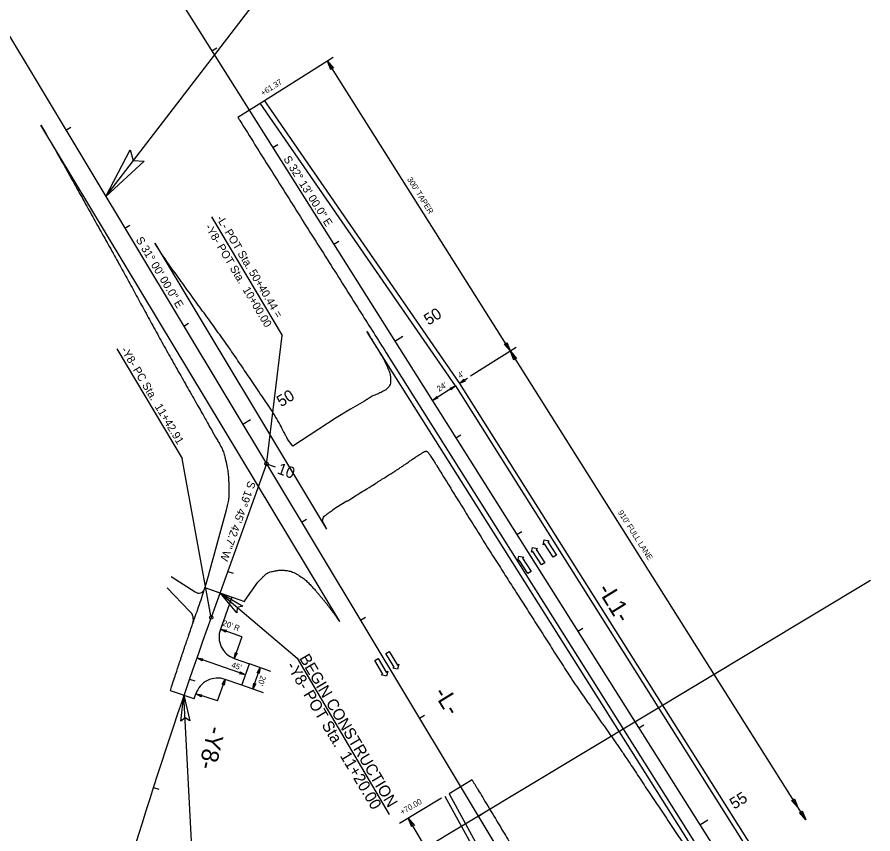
# Model space of a CAD drawing. Extents: x 1778969 to 1790720, y 807089 to 817794.
# Drawn here: x 1781066 to 1781814, y 813902 to 814616 of the extents above; entities that cross this region are included whole.
import ezdxf

# ---------------------------------------------------------------- set-up
doc = ezdxf.new("R2010")
doc.units = 0
for name, color, linetype in [('Default', 7, 'Continuous'), ('Prop Dimension', 7, 'Continuous'), ('Prop Dimension Text', 7, 'Continuous'), ('Prop EOT', 7, 'Continuous'), ('Prop Horizontal Alignment', 7, 'Continuous'), ('Prop Horizontal Alignment Direction Label', 7, 'Continuous'), ('Prop Horizontal Alignment Station Label', 7, 'Continuous'), ('Prop Horizontal Alignment Tick Label', 7, 'Continuous'), ('Prop Horizontal Alignment Tick Large', 7, 'Continuous'), ('Prop Horizontal Alignment Tick Small', 7, 'Continuous'), ('Prop Lane Arrow CELL', 7, 'Continuous'), ('Prop Paved Shoulder', 7, 'Continuous'), ('Prop Rem of Exist Asph Pvmt', 7, 'Continuous'), ('Prop Terminator CELL', 7, 'Continuous'), ('Scratch_Level_1', 7, 'Continuous')]:
    doc.layers.add(name, color=color, linetype=linetype)

msp = doc.modelspace()

# ---------------------------------------------------------------- linework, layer by layer
at = {"layer": 'Default'}
msp.add_line((1781346.69, 814088.87), (1781347.63, 814087.49), dxfattribs=at)
at = {"layer": 'Prop Dimension'}
for p, q in [((1781341.9, 814580.9), (1781281.87, 814543.07)), ((1781496.79, 814323.91), (1781336.86, 814577.72)), ((1781501.83, 814327.09), (1781462.04, 814302.01)), ((1781754.93, 813914.26), (1781496.79, 814323.91)), ((1781459.23, 814300.24), (1781452.3, 814295.87)), ((1781448.91, 814293.74), (1781428.61, 814280.94)), ((1781262.15, 814074.06), (1781243.31, 814080.8)), ((1781262.15, 814074.06), (1781255.49, 814055.2)), ((1781265.28, 814040.96), (1781222.81, 814055.83)), ((1781287.53, 814043.95), (1781268.66, 814050.56)), ((1781271.58, 814028.34), (1781278.19, 814047.22)), ((1781240.88, 814018.08), (1781247.45, 814036.97)), ((1781280.99, 814025.26), (1781262.11, 814031.87)), ((1781240.88, 814018.08), (1781221.86, 814024.26)), ((1781436.57, 813932.96), (1781399.86, 813910.91)), ((1781562.09, 813658.39), (1781407.57, 813915.54))]:
    msp.add_line(p, q, dxfattribs=at)
at = {"layer": 'Prop EOT'}
for p, q in [((1781281.87, 814543.07), (1781258.57, 814528.39)), ((1781448.91, 814293.74), (1781278.22, 814540.77)), ((1781388.28, 814322.43), (1781718.05, 813799.1)), ((1781448.91, 814293.74), (1781832.66, 813684.75)), ((1781200.42, 814127.05), (1781221.29, 814113.54)), ((1781196.86, 814117.14), (1781216.27, 814096.74)), ((1781229.78, 814117.37), (1781253.4, 814108.89)), ((1781253.4, 814108.89), (1781245.65, 814087.33)), ((1781217.08, 814079.71), (1781216.98, 814079.42)), ((1781255.49, 814055.2), (1781268.66, 814050.56)), ((1781262.11, 814031.87), (1781268.66, 814050.56)), ((1781262.11, 814031.87), (1781247.45, 814036.97)), ((1781220.45, 814019.94), (1781199.59, 814027.07)), ((1781220.45, 814019.94), (1781221.86, 814024.26)), ((1781463.3, 813949.03), (1781443.19, 813936.94)), ((1781443.19, 813936.94), (1781587.3, 813673.54))]:
    msp.add_line(p, q, dxfattribs=at)
for centre, radius, start, end in [((1781224.56, 814117.32), 5, 229.17438, 343.68233), ((1781209.73, 814089.17), 10, 341.35053, 49.17438), ((1785549.01, 812541.26), 4572.66, 160.23814, 160.32504), ((1781262.15, 814074.06), 20, 160.32504, 250.57674), ((1781240.88, 814018.08), 20, 70.82674, 161.99515)]:
    msp.add_arc(centre, radius, start, end, dxfattribs=at)
msp.add_spline([(1781258.57, 814528.39), (1781260.31, 814525.62), (1781286.77, 814483.59), (1781313.25, 814441.37), (1781340.02, 814399.05), (1781366.32, 814357.37), (1781388.28, 814322.43)], degree=3, dxfattribs=at)
for points in [[(1781199.59, 814027.07), (1781201.21, 814032.08), (1781202.84, 814037.08), (1781204.47, 814042.09), (1781208.13, 814053.3), (1781211.9, 814064.48), (1781215.69, 814075.65), (1781217.58, 814081.21), (1781219.55, 814086.75), (1781221.45, 814092.3), (1781224.25, 814100.43), (1781227.25, 814108.5), (1781229.61, 814116.76), (1781229.67, 814116.96), (1781229.72, 814117.17), (1781229.78, 814117.37)], [(1781463.3, 813949.03), (1781464.17, 813947.59), (1781465.05, 813946.15), (1781465.92, 813944.71), (1781474.8, 813929.99), (1781483.67, 813915.26), (1781492.5, 813900.51), (1781500.58, 813887.01), (1781508.59, 813873.47), (1781516.69, 813859.98), (1781525.21, 813845.83), (1781533.74, 813831.69), (1781542.26, 813817.54), (1781551.3, 813802.52), (1781560.33, 813787.49), (1781569.37, 813772.46), (1781578.14, 813757.89), (1781587.14, 813743.46), (1781595.91, 813728.89), (1781604.33, 813714.9), (1781612.49, 813700.76), (1781620.9, 813686.76), (1781629.44, 813672.57), (1781637.98, 813658.38), (1781646.54, 813644.19), (1781655.1, 813630), (1781663.72, 813615.84), (1781672.26, 813601.63), (1781680.69, 813587.61), (1781689, 813573.52), (1781697.41, 813559.48), (1781705.95, 813545.23), (1781714.52, 813530.99), (1781723.07, 813516.73), (1781731.64, 813502.44), (1781740.12, 813488.1), (1781748.7, 813473.81), (1781757.55, 813459.07), (1781766.63, 813444.47), (1781775.52, 813429.74), (1781784.14, 813415.46), (1781792.67, 813401.11), (1781801.32, 813386.83), (1781809.96, 813372.55), (1781818.65, 813358.29), (1781827.3, 813344.02), (1781835.99, 813329.66), (1781844.67, 813315.3), (1781853.35, 813300.93), (1781861.54, 813287.37), (1781869.6, 813273.73), (1781877.8, 813260.18), (1781886.68, 813245.53), (1781895.77, 813231.01), (1781904.68, 813216.38), (1781913.11, 813202.51), (1781921.54, 813188.63), (1781929.97, 813174.75), (1781938.85, 813160.12), (1781947.7, 813145.46), (1781956.59, 813130.83), (1781964.95, 813117.07), (1781973.52, 813103.43), (1781982.19, 813089.85), (1781991.2, 813075.72), (1782000.27, 813061.63), (1782009.36, 813047.54), (1782018.57, 813033.28), (1782027.8, 813019.03), (1782037.07, 813004.8), (1782046.22, 812990.76), (1782055.4, 812976.74), (1782064.84, 812962.89), (1782074.16, 812949.23), (1782083.5, 812935.58), (1782092.82, 812921.91), (1782102.18, 812908.19), (1782111.54, 812894.47), (1782120.9, 812880.75), (1782130.3, 812866.98), (1782139.85, 812853.32), (1782149.42, 812839.67), (1782158.88, 812826.17), (1782168.45, 812812.74), (1782178.15, 812799.41), (1782187.7, 812786.29), (1782197.57, 812773.41), (1782207.08, 812760.26), (1782216.45, 812747.28), (1782225.83, 812734.3), (1782235.2, 812721.32)]]:
    msp.add_open_spline(points, degree=3, dxfattribs=at)
at = {"layer": 'Prop Horizontal Alignment'}
for p, q in [((1780487.95, 815773.73), (1781812.35, 813671.96)), ((1780487.95, 815773.73), (1781812.35, 813671.96)), ((1780459.21, 815597.59), (1781830.87, 813314.76)), ((1780459.21, 815597.59), (1781830.87, 813314.76)), ((1781283.62, 814225.54), (1781235.3, 814091.04))]:
    msp.add_line(p, q, dxfattribs=at)
msp.add_arc((1785549.01, 812541.26), 4583.66, 160.23814, 164.70285, dxfattribs=at)
at = {"layer": 'Prop Horizontal Alignment Station Label'}
for p, q in [((1781143.14, 814459.33), (1781295.69, 814658.05)), ((1781235.5, 814441.55), (1781297.3, 814337.6)), ((1781283.8, 814227.03), (1781297.3, 814337.6)), ((1781152.75, 814326.03), (1781209.78, 814230.09)), ((1781235.03, 814092.52), (1781209.78, 814230.09)), ((1781243.05, 814112.61), (1781310.31, 814055.63)), ((1781310.31, 814055.63), (1781390.85, 813918.77)), ((1781222.21, 813816.09), (1781211.46, 814023.01))]:
    msp.add_line(p, q, dxfattribs=at)
for centre in [(1781283.62, 814225.54), (1781283.62, 814225.54), (1781235.3, 814091.04)]:
    msp.add_circle(centre, 1.5, dxfattribs=at)
at = {"layer": 'Prop Horizontal Alignment Tick Large'}
for p, q in [((1781395.89, 814332.87), (1781402.66, 814337.13)), ((1781262.79, 814260.2), (1781269.65, 814264.32)), ((1781283.62, 814225.54), (1781291.15, 814222.84)), ((1781283.62, 814225.54), (1781291.15, 814222.84)), ((1781662.45, 813909.85), (1781669.22, 813914.11))]:
    msp.add_line(p, q, dxfattribs=at)
at = {"layer": 'Prop Horizontal Alignment Tick Small'}
for p, q in [((1781235.95, 814586.68), (1781240.18, 814589.34)), ((1781108.28, 814517.35), (1781112.57, 814519.93)), ((1781289.27, 814502.07), (1781293.5, 814504.74)), ((1781159.79, 814431.64), (1781164.07, 814434.21)), ((1781342.58, 814417.47), (1781346.81, 814420.13)), ((1781211.29, 814345.92), (1781215.58, 814348.49)), ((1781449.2, 814248.26), (1781453.43, 814250.93)), ((1781314.3, 814174.49), (1781318.58, 814177.06)), ((1781502.52, 814163.66), (1781506.75, 814166.32)), ((1781249.81, 814131.43), (1781254.52, 814129.74)), ((1781365.8, 814088.77), (1781370.09, 814091.34)), ((1781555.83, 814079.05), (1781560.06, 814081.72)), ((1781216.33, 814037.2), (1781221.06, 814035.57)), ((1781417.3, 814003.05), (1781421.59, 814005.63)), ((1781609.14, 813994.45), (1781613.37, 813997.12)), ((1781184.73, 813942.33), (1781189.49, 813940.8)), ((1781468.81, 813917.34), (1781473.09, 813919.91))]:
    msp.add_line(p, q, dxfattribs=at)
at = {"layer": 'Prop Lane Arrow CELL'}
for p, q in [((1781515.15, 814148.07), (1781516.06, 814152.4)), ((1781516.06, 814152.4), (1781520.45, 814151.48)), ((1781525.48, 814154.7), (1781526.38, 814159.03)), ((1781526.74, 814155.51), (1781525.48, 814154.7)), ((1781526.38, 814159.03), (1781530.78, 814158.11)), ((1781534.31, 814143.73), (1781526.74, 814155.51)), ((1781530.78, 814158.11), (1781529.52, 814157.3)), ((1781529.52, 814157.3), (1781537.08, 814145.52)), ((1781503.33, 814140.48), (1781504.23, 814144.8)), ((1781504.23, 814144.8), (1781508.63, 814143.88)), ((1781516.41, 814148.88), (1781515.15, 814148.07)), ((1781523.98, 814137.1), (1781516.41, 814148.88)), ((1781520.45, 814151.48), (1781519.19, 814150.67)), ((1781519.19, 814150.67), (1781526.76, 814138.89)), ((1781537.08, 814145.52), (1781534.31, 814143.73)), ((1781504.59, 814141.29), (1781503.33, 814140.48)), ((1781512.16, 814129.51), (1781504.59, 814141.29)), ((1781508.63, 814143.88), (1781507.37, 814143.07)), ((1781507.37, 814143.07), (1781514.93, 814131.29)), ((1781526.76, 814138.89), (1781523.98, 814137.1)), ((1781514.93, 814131.29), (1781512.16, 814129.51)), ((1781378.25, 814053.59), (1781381.09, 814055.27)), ((1781381.09, 814055.27), (1781388.24, 814043.24)), ((1781388.02, 814059.7), (1781390.86, 814061.39)), ((1781395.18, 814047.67), (1781388.02, 814059.7)), ((1781390.86, 814061.39), (1781398.01, 814049.35)), ((1781385.4, 814041.55), (1781378.25, 814053.59)), ((1781393.89, 814046.9), (1781395.18, 814047.67)), ((1781398.01, 814049.35), (1781399.3, 814050.12)), ((1781399.3, 814050.12), (1781398.25, 814045.83)), ((1781384.11, 814040.79), (1781385.4, 814041.55)), ((1781388.48, 814039.71), (1781384.11, 814040.79)), ((1781388.24, 814043.24), (1781389.53, 814044.01)), ((1781389.53, 814044.01), (1781388.48, 814039.71)), ((1781398.25, 814045.83), (1781393.89, 814046.9))]:
    msp.add_line(p, q, dxfattribs=at)
at = {"layer": 'Prop Paved Shoulder'}
for p, q in [((1781281.87, 814543.07), (1781452.3, 814295.87)), ((1781452.3, 814295.87), (1781836.04, 813686.89)), ((1781439.63, 813934.8), (1781583.87, 813671.48))]:
    msp.add_line(p, q, dxfattribs=at)
at = {"layer": 'Prop Rem of Exist Asph Pvmt'}
for p, q in [((1781347.63, 814087.49), (1781086.3, 814521.67)), ((1781186.06, 814418.34), (1781336.16, 814168.44)), ((1781710.88, 813802.98), (1781371.34, 814341.26)), ((1781369.2, 814280.41), (1781356.96, 814273.28)), ((1781240.67, 814246.06), (1781241.22, 814245.41)), ((1781344.85, 814187.68), (1781353.97, 814192.98)), ((1781353.97, 814192.98), (1781354.7, 814193.2)), ((1781248.38, 814184.99), (1781233.25, 814129.52)), ((1781229.78, 814117.37), (1781264.25, 814104.99)), ((1781264.94, 814106.16), (1781276.07, 814122.01)), ((1781346.69, 814088.87), (1781347.63, 814087.49))]:
    msp.add_line(p, q, dxfattribs=at)
msp.add_lwpolyline([(1781356.96, 814273.28), (1781344.53, 814265.75), (1781306.61, 814240.93), (1781301.99, 814247.17)], dxfattribs=at)
for points, degree in [([(1781086.3, 814521.67), (1781092.84, 814510.56), (1781099.4, 814499.46), (1781105.7, 814488.21), (1781114.06, 814473.27), (1781122.35, 814458.29), (1781130.69, 814443.34), (1781139.04, 814428.38), (1781147.42, 814413.44), (1781155.75, 814398.47), (1781163.36, 814384.8), (1781170.69, 814370.97), (1781178.23, 814357.25), (1781186.23, 814342.69), (1781194.2, 814328.1), (1781202.39, 814313.64), (1781210.68, 814299), (1781218.98, 814284.38), (1781227.27, 814269.74), (1781231.74, 814261.85), (1781236.21, 814253.96), (1781240.67, 814246.06)], 3), ([(1781301.99, 814247.17), (1781300.93, 814249.17), (1781299.88, 814251.18), (1781298.83, 814253.18), (1781290.68, 814268.72), (1781280.64, 814283.19), (1781270.82, 814297.74), (1781262.02, 814310.79), (1781253.18, 814323.8), (1781244.04, 814336.62), (1781234.12, 814350.54), (1781223.91, 814364.26), (1781213.98, 814378.18), (1781204.51, 814391.45), (1781194.76, 814404.55), (1781186.06, 814418.34)], 3), ([(1781371.34, 814341.26), (1781375.17, 814334.98), (1781378.98, 814328.69), (1781382.81, 814322.4), (1781385.34, 814318.23), (1781387.45, 814314.08), (1781389.52, 814309.42), (1781391.2, 814305.65), (1781392.1, 814301.76), (1781392.1, 814297.89), (1781392.1, 814296.91), (1781391.95, 814295.88), (1781391.6, 814294.95)], 3), ([(1781391.6, 814294.95), (1781391.25, 814293.99), (1781390.76, 814293.11), (1781390.07, 814292.31), (1781388.94, 814290.97), (1781387.56, 814290.02), (1781386.07, 814289.2), (1781381.75, 814286.82), (1781377.03, 814285.31), (1781372.87, 814282.71), (1781371.64, 814281.94), (1781370.42, 814281.17), (1781369.2, 814280.41)], 3), ([(1781241.22, 814245.41), (1781242.26, 814243.47), (1781243.31, 814241.53), (1781244.36, 814239.59), (1781244.66, 814239.03), (1781244.93, 814238.45), (1781245.17, 814237.86), (1781245.97, 814235.83), (1781246.59, 814233.76), (1781247.14, 814231.66), (1781247.61, 814229.9), (1781248.04, 814228.14), (1781248.44, 814226.37), (1781248.76, 814224.93), (1781249.06, 814223.5), (1781249.31, 814222.05), (1781249.74, 814219.52), (1781250.05, 814216.98), (1781250.26, 814214.42), (1781250.48, 814211.83), (1781250.6, 814209.24), (1781250.7, 814206.64), (1781250.79, 814204.01), (1781250.8, 814201.37), (1781250.72, 814198.73), (1781250.64, 814196.23), (1781250.46, 814193.71), (1781249.88, 814191.27), (1781249.38, 814189.18), (1781248.88, 814187.09), (1781248.38, 814184.99)], 3), ([(1781354.7, 814193.2), (1781362.1, 814197.98), (1781369.62, 814202.58), (1781377.09, 814207.26), (1781381.34, 814209.93), (1781385.59, 814212.6), (1781389.84, 814215.27), (1781393.21, 814217.38), (1781396.55, 814219.56), (1781399.89, 814221.73), (1781401.28, 814222.63), (1781402.67, 814223.54), (1781404.04, 814224.48), (1781405.47, 814225.46), (1781406.88, 814226.46), (1781408.3, 814227.45), (1781409.76, 814228.47), (1781411.22, 814229.51), (1781412.7, 814230.5), (1781414.2, 814231.51), (1781415.73, 814232.46), (1781417.24, 814233.44), (1781418.13, 814234.01), (1781419.03, 814234.59), (1781419.93, 814235.16), (1781420.37, 814235.44), (1781420.82, 814235.67), (1781421.29, 814235.93), (1781421.73, 814236.17), (1781422.19, 814236.39), (1781422.64, 814236.53), (1781423.18, 814236.71), (1781423.79, 814236.37), (1781424.29, 814235.94), (1781424.93, 814235.39), (1781425.28, 814234.84), (1781425.7, 814234.23), (1781426.81, 814232.59), (1781427.96, 814230.98), (1781429.01, 814229.3), (1781430.05, 814227.64), (1781431.09, 814225.99), (1781432.12, 814224.33), (1781441.22, 814209.63), (1781450.27, 814194.9), (1781459.4, 814180.22), (1781468.54, 814165.52), (1781477.72, 814150.84), (1781487.02, 814136.24), (1781495.53, 814122.88), (1781504.12, 814109.56), (1781512.65, 814096.21), (1781521.67, 814082.1), (1781530.59, 814067.94), (1781539.63, 814053.84), (1781548.76, 814039.6), (1781558.29, 814025.61), (1781567.87, 814011.67), (1781570.25, 814008.21), (1781572.62, 814004.76), (1781575.04, 814001.33), (1781577.45, 813997.9), (1781579.87, 813994.47), (1781582.29, 813991.04), (1781584.7, 813987.61), (1781587.12, 813984.17), (1781589.53, 813980.73), (1781591.95, 813977.28), (1781594.32, 813973.81), (1781596.68, 813970.32), (1781605.82, 813956.77), (1781614.69, 813943.04), (1781623.79, 813929.47), (1781633.2, 813915.43), (1781642.63, 813901.4), (1781652.24, 813887.49), (1781654.56, 813884.14), (1781656.9, 813880.81), (1781659.28, 813877.5), (1781661.67, 813874.19), (1781664.06, 813870.88), (1781666.44, 813867.57), (1781668.83, 813864.25), (1781671.22, 813860.93), (1781673.61, 813857.62), (1781676.01, 813854.3), (1781678.36, 813850.95), (1781680.69, 813847.59), (1781682.57, 813844.89), (1781684.45, 813842.18), (1781686.32, 813839.47)], 3), ([(1781336.16, 814168.44), (1781335.48, 814169.78), (1781334.81, 814171.12), (1781334.13, 814172.47), (1781333.31, 814174.12), (1781332.27, 814176.29), (1781333.09, 814177.9), (1781333.98, 814179.64), (1781335.69, 814181.01), (1781337.32, 814182.2), (1781339.83, 814184.02), (1781342.34, 814185.85), (1781344.85, 814187.68)], 3), ([(1781276.07, 814122.01), (1781277.71, 814123.67), (1781279.35, 814125.34), (1781280.99, 814127), (1781282.11, 814128.13), (1781283.27, 814129.19), (1781284.73, 814129.97), (1781286.75, 814131.05), (1781288.93, 814131.4), (1781291.13, 814131.81), (1781292.76, 814132.11), (1781294.38, 814132.38), (1781296.01, 814132.46), (1781297.58, 814132.54), (1781299.17, 814132.41), (1781300.74, 814132.19), (1781302.62, 814131.93), (1781304.46, 814131.56), (1781306.24, 814130.83), (1781308.6, 814129.88), (1781310.71, 814128.66), (1781312.81, 814127.29), (1781314.69, 814126.07), (1781316.55, 814124.88), (1781318.19, 814123.37), (1781319.66, 814122.01), (1781321.05, 814120.6), (1781322.4, 814119.13), (1781323.63, 814117.79), (1781324.87, 814116.45), (1781326.06, 814115.07), (1781327.74, 814113.14), (1781329.39, 814111.19), (1781331.04, 814109.24), (1781332.79, 814107.15), (1781334.57, 814105.08), (1781336.24, 814102.92), (1781337.79, 814100.92), (1781339.3, 814098.88), (1781340.81, 814096.85), (1781342.77, 814094.19), (1781344.73, 814091.53), (1781346.69, 814088.87)], 3), ([(1781233.25, 814129.52), (1781232.1, 814125.47), (1781230.94, 814121.42), (1781229.78, 814117.37)], 2), ([(1781264.25, 814104.99), (1781264.48, 814105.38), (1781264.71, 814105.77), (1781264.94, 814106.16)], 2)]:
    msp.add_open_spline(points, degree=degree, dxfattribs=at)
at = {"layer": 'Prop Terminator CELL'}
for points in [[(1781339.83, 814570.06), (1781336.86, 814577.72), (1781342.29, 814571.48), (1781340.52, 814571.63)], [(1781176.69, 814490.31), (1781143.14, 814459.33), (1781164.35, 814500.1), (1781167.2, 814490.66)], [(1781493.68, 814331.52), (1781496.79, 814323.91), (1781491.25, 814330.05), (1781493.02, 814329.94)], [(1781499.77, 814316.25), (1781496.79, 814323.91), (1781502.22, 814317.67), (1781500.46, 814317.82)], [(1781457.16, 814297.88), (1781452.3, 814295.87), (1781456.22, 814299.43), (1781456.15, 814298.3)], [(1781444.05, 814291.73), (1781448.91, 814293.74), (1781444.99, 814290.18), (1781445.06, 814291.31)], [(1781433.47, 814282.95), (1781428.61, 814280.94), (1781432.53, 814284.5), (1781432.46, 814283.37)], [(1781257.71, 814095.11), (1781243.05, 814112.61), (1781262.9, 814101.04), (1781258.12, 814099.84)], [(1781247.89, 814078.2), (1781243.31, 814080.8), (1781248.53, 814079.9), (1781247.6, 814079.26)], [(1781227.39, 814053.23), (1781222.81, 814055.83), (1781228.03, 814054.93), (1781227.09, 814054.29)], [(1781258.09, 814059.78), (1781255.49, 814055.2), (1781256.39, 814060.42), (1781257.03, 814059.48)], [(1781260.71, 814043.55), (1781265.28, 814040.96), (1781260.06, 814041.85), (1781261, 814042.5)], [(1781275.6, 814042.64), (1781278.19, 814047.22), (1781277.3, 814042), (1781276.66, 814042.94)], [(1781244.85, 814032.39), (1781247.45, 814036.97), (1781246.55, 814031.75), (1781245.91, 814032.69)], [(1781274.18, 814032.92), (1781271.58, 814028.34), (1781272.48, 814033.56), (1781273.12, 814032.63)], [(1781208.72, 814000.35), (1781211.46, 814023.01), (1781216.59, 814000.62), (1781212.45, 814003.29)], [(1781226.43, 814021.67), (1781221.86, 814024.26), (1781227.07, 814023.37), (1781226.14, 814022.72)], [(1781744.99, 813932.58), (1781748.11, 813924.97), (1781742.57, 813931.11), (1781744.34, 813931)], [(1781751.82, 813921.87), (1781754.93, 813914.26), (1781749.39, 813920.4), (1781751.16, 813920.29)], [(1781410.55, 813907.88), (1781407.57, 813915.54), (1781413, 813909.3), (1781411.24, 813909.45)]]:
    msp.add_lwpolyline(points, close=True, dxfattribs=at)
at = {"layer": 'Scratch_Level_1'}
msp.add_line((1781811.68, 814123.35), (1781125.94, 813711.32), dxfattribs=at)

# ---------------------------------------------------------------- texts
at = {"layer": 'Prop Dimension Text'}
for s, rotation, p in [('+61.37', 32.49712, (1781280.47, 814547.02)), ("300' TAPER", 302.21667, (1781406.27, 814474.36)), ("4'", 31.68595, (1781452.54, 814300.07)), ("24'", 31.68595, (1781434.4, 814288.39)), ("910' FULL LANE", 302.42697, (1781590.58, 814182.94)), ("20' R", 339.81645, (1781244.73, 814084.26)), ("45'", 341.55535, (1781252.52, 814047.58)), ("20'", 250.67075, (1781278.64, 814040.79)), ('+70.00', 30.16124, (1781402.15, 813918.31))]:
    msp.add_text(s, height=5, rotation=rotation, dxfattribs=at).set_placement(p)
at = {"layer": 'Prop Horizontal Alignment Direction Label'}
for s, rotation, p in [('S 32%%d 13\' 00.0" E', 302.21667, (1781298.13, 814492.17)), ('S 31%%d 00\' 00.0" E', 301, (1781169.13, 814421.49)), ('S 19%%d 45\' 42.7" W', 250.23814, (1781267.76, 814211.08))]:
    msp.add_text(s, height=7, rotation=rotation, dxfattribs=at).set_placement(p)
at = {"layer": 'Prop Horizontal Alignment Station Label'}
for s, height, rotation, p in [('-L- POT Sta. 50+40.44 =', 7, 300.93035, (1781239.54, 814440.23)), ('-Y8- POT Sta.  10+00.00', 7, 300.93035, (1781229.6, 814432.65)), ('-Y8- PC Sta.  11+42.91', 7, 300.80913, (1781156.14, 814325.17)), ('-L1-', 15, 301.59203, (1781572.32, 814115.57)), ('BEGIN CONSTRUCTION', 10, 300.775, (1781311.93, 814055.5)), ('-Y8- POT Sta.  11+20.00', 10, 300.775, (1781300.67, 814048.8)), ('-L-', 15, 301.59203, (1781429.18, 814024.96)), ('-Y8-', 15, 256.58782, (1781233.07, 813996.95))]:
    msp.add_text(s, height=height, rotation=rotation, dxfattribs=at).set_placement(p)
at = {"layer": 'Prop Horizontal Alignment Tick Label'}
for s, rotation, p in [('50', 32.21667, (1781425.16, 814346.28)), ('50', 31, (1781296.31, 814274.84)), ('10', 340.23814, (1781292.25, 814217.22)), ('55', 32.21667, (1781692.42, 813922.93))]:
    msp.add_text(s, height=10, rotation=rotation, dxfattribs=at).set_placement(p)

doc.saveas('drawing.dxf')
